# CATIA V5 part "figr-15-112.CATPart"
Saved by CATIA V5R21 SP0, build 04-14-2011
Part number: Part1
Bounding box of the stored display mesh (mm): x -55.37 to 68.649, y -21.457 to 35.984, z 0 to 57.441
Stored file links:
  D:\CATIA V5R21 E-RESOURCES\CATIA-V5R21\catia-v5r21-prt\c15-catia-v5r20-prt\c15-catia-v5r21-figr-15-112.CATPart
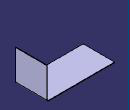
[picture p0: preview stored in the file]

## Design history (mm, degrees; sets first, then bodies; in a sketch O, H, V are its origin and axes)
SheetMetalParameters1: Thickness 1, BendRadius 2, KFactor 0.400515 {= log(min(100,max(20*SheetMetalParameters1.BendRadius,SheetMetalParameters1.Thickness)/SheetMetalParameters1.Thickness))/log(100)/2}, ReliefRadialLength 1, ReliefAxialLength 2, MinimumBendRadius 0
Body1 (main body)
  Sketch1 on xy-plane, origin (0, 0, 0), H (1, 0, 0), V (0, 1, 0)
    line L1 (-55.3695, 35.9836) -> (67.649, 35.9836)
    line L2 (67.649, 35.9836) -> (67.649, -21.4575)
    line L3 (67.649, -21.4575) -> (-55.3695, -21.4575)
    line L4 (-55.3695, -21.4575) -> (-55.3695, 35.9836)
    horizontal: L1 H, L3 H
    vertical: L2 V, L4 V
  Wall1: Thickness 1, Profile Sketch1
  d_NewWallOnEdge1: NewWallOnEdge_Edge edge [face of Wall1 | face of Wall1], NewWallOnEdge_Length 57.4411, NewWallOnEdge_HeightLimitOffset 0, NewWallOnEdge_WidthOffset1 0, NewWallOnEdge_WidthOffset2 0, NewWallOnEdge_Angle 90, NewWallOnEdge_BendRadiusValue 2 {= SheetMetalParameters1.BendRadius}, NewWallOnEdge_BendTable SheetMetalParameters1, KFacteur 0.400515 {= log(min(100,max(20*d_NewWallOnEdge1.Radius,SheetMetalParameters1.Thickness)/SheetMetalParameters1.Thickness))/log(100)/2}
